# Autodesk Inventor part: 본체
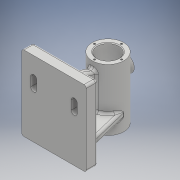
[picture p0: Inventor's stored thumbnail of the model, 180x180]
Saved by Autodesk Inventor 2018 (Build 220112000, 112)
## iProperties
Created: 2022-06
Part Number: 본체
Material: 일반
Document SubType Name: Modeling
Designer: home
Density: 1 g/cm^3
Appearance: 기본값
Author: home
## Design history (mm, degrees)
sketch "스케치1"
  geometry: L1 (-43, 50)-(43, 50); L2 (43, 50)-(43, -50); L3 (43, -50)-(-43, -50); L4 (-43, -50)-(-43, 50); L5 (-43, 50)-(43, -50); L6 (43, 50)-(-43, -50); 1 further point
  constraints: 12 end point, 2 midpoint, 2 parallel, 1 horizontal, 1 perpendicular
  dimensions: "d0" = 86 distance of L2.end L3.end; "d1" = 100 distance of L1.end L2.end
extrude "돌출1" new body sketch "스케치1" distance "d2" = 15; taper "d3" = 0 deg
sketch "스케치2"
  geometry: L1 (72, 71.237)-(72, -101.318); L2 (83.5, -50)-(93, -50); L3 (0, -50)-(15, -50) reference; L4 (83.5, -50)-(83.5, -30); L5 (93, -50)-(93, -20.658); L6 (93, -20.658)-(93, 32); L7 (93, 32)-(86.5, 32); L8 (86.5, 32)-(86.5, -30); L9 (86.5, -30)-(83.5, -30); 1 further point
  constraints: 16 end point, 3 perpendicular, 3 vertical, 2 horizontal
  dimensions: "d4" = 144 diameter of point (0, 0) L1; "d5" = 0 distance between parallel lines of L2 L3; "d6" = 23 diameter of L4 L1; "d7" = 42 diameter of L5 L1; "d8" = 82 distance of L2.end L6.end; "d9" = 29 diameter of L8 L1; "d10" = 62 vertical distance of L7.end L4.end
revolve "회전1" sketch "스케치2" stored, may be unused: angle "d11" = 90 deg
node "작업 평면1"
sketch "스케치5"
  geometry: L1 (0, 0)-(0, 15) reference; L2 (86, 15)-(0, 15) reference; L3 (8, 15)-(22, 72); L4 (43, 72)-(0, 72); L5 (43, 0)-(43, 72); L6 (0, 0)-(86, 0) reference; L7 (78, 15)-(64, 72); L8 (8, 15)-(78, 15); L9 (8, 15)-(78, 15); A1 r 21 centre (43, 72) between (22, 72) and (64, 72); A2 r 21 centre (43, 72) between (22, 72) and (64, 72)
  constraints: 12 end point, 4 point on circle, 2 centre point, 2 horizontal, 2 symmetric about line, 1 collinear, 1 concentric, 1 horizontal alignment, 1 perpendicular, 1 other
  dimensions: "d13" = 8 distance from line of L1 L3.start; "d14" = 0 distance from line of L2 L3.start; "d15" = 103.799 deg angle of L2 L3
extrude "돌출2" join sketch "스케치5" distance "d16" = 10; taper "d17" = 0 deg
node "작업 평면2"
sketch "스케치6"
  geometry: L1 (0, 0)-(0, 15) reference; L2 (100, 15)-(0, 15) reference; L3 (15, 15)-(28.823, 52.978); L4 (75, 72)-(75, 15) reference; L5 (15, 15)-(75, 15); L6 (75, 52.978)-(28.823, 52.978); L7 (18, 51)-(100, 51) reference; L8 (75, 52.978)-(75, 15); 2 further points
  constraints: 8 end point, 1 collinear, 1 parallel, 1 point on line
  dimensions: "d18" = 15 distance from line of L1 L3.start; "d19" = 0 distance from line of L2 L3.start; "d20" = 70 deg angle of L2 L3; "d21" = 0 distance from line of L4 point (75, 15); "d22" = 0 distance of L4.end point (75, 15); "d23" = 46.17723 distance of L6.start L3.end
extrude "돌출3" join sketch "스케치6" stored distance "d24" = 10; taper "d25" = 0 deg
node "작업 평면3"
sketch "스케치7"
  geometry: L1 (-21, 32)-(21, 32) reference; C1 r 11 at (0, 7); 2 further points
  constraints: 1 centre point, 1 coincident
  dimensions: "d27" = 25 distance from line of L1 point (0, 7); "d28" = 0 horizontal distance of point (0, 0) point (0, 7); "d29" = 22 diameter of C1
extrude "돌출4" join sketch "스케치7" stored distance "d30" = 10; taper "d31" = 0 deg; dims "d11" = 90 deg
sketch "스케치8"
  geometry: C1 r 11 at (0, 0) reference; C2 r 7 at (0, 0); 1 further point
  constraints: 1 centre point, 1 coincident
  dimensions: "d32" = 14 diameter of C2
extrude "돌출5" cut sketch "스케치8" distance "d33" = 4; taper "d34" = 0 deg
sketch "스케치9"
  geometry: C1 r 7 at (0, 0) reference; 1 further point
hole "구멍1" sketch "스케치9" at (0, 0) diameter "d35" = 4.917; stored, may be unused: countersink angle "d39" = 90 deg, drill point angle "d41" = 0 deg; dims "d36" = 15, "d37" = 4, "d38" = 2, "d40" = 15
fillet "모깎기1" dims "d42" = 1
sketch "스케치10"
  geometry: C1 r 14.5 at (0, 0) reference; C2 r 21 at (0, 0) reference; 2 further points
  dimensions: "d43" = 0 horizontal distance of C1.centre point (0, 18); "d44" = 18 distance of C1.centre point (0, 18)
hole "구멍2" sketch "스케치10" at (0, 18) diameter "d45" = 2.459; stored, may be unused: countersink angle "d49" = 90 deg, drill point angle "d51" = 118 deg; dims "d46" = 8, "d47" = 4, "d48" = 2, "d50" = 10
sketch "스케치11"
  geometry: C1 r 21 at (0, 0) reference; C2 r 11.5 at (0, 0) reference; 2 further points
  dimensions: "d55" = 0 horizontal distance of C1.centre point (0, 18); "d56" = 18 distance of C1.centre point (0, 18)
hole "구멍3" sketch "스케치11" at (0, 18) diameter "d57" = 2.459; stored, may be unused: countersink angle "d61" = 90 deg, drill point angle "d63" = 118 deg; dims "d58" = 8, "d59" = 4, "d60" = 2, "d62" = 10
node "작업 평면4"
sketch "스케치12"
  geometry: L1 (-43, -50)-(43, -50) reference; L2 (27, -24)-(27, -12); L3 (34, -24)-(34, -12); L4 (20, -12)-(20, -24); L5 (27, -24)-(27, -12); L6 (31, -24)-(31, -12); L7 (23, -12)-(23, -24); L8 (0, -57.693)-(0, 78.656); L9 (-20, -12)-(-20, -24); L10 (-23, -12)-(-23, -24); L11 (-31, -24)-(-31, -12); L12 (-34, -24)-(-34, -12); A1 r 7 centre (27, -24) between (20, -24) and (34, -24); A2 r 7 centre (27, -12) between (34, -12) and (20, -12); A3 r 4 centre (27, -24) between (23, -24) and (31, -24); A4 r 4 centre (27, -12) between (31, -12) and (23, -12); A5 r 7 centre (-27, -24) between (-34, -24) and (-20, -24); A6 r 7 centre (-27, -12) between (-20, -12) and (-34, -12); A7 r 4 centre (-27, -24) between (-31, -24) and (-23, -24); A8 r 4 centre (-27, -12) between (-23, -12) and (-31, -12); 3 further points
  constraints: 26 end point, 16 point on circle, 10 symmetric about line, 8 centre point, 8 tangent, 3 equal length, 2 midpoint, 2 vertical, 4 other
  dimensions: "d68" = 27 horizontal distance of L2.start point (0, 0); "d69" = 26 distance from line of L1 L2.start; "d70" = 12 distance of L2.start L2.end; "d71" = 14 diameter of A2; "d72" = 8 diameter of A4; "d73" = 0 distance from line of L8 point (0, 0)
extrude "돌출6" join sketch "스케치12" stored distance "d74" = 4; taper "d75" = 0 deg
sketch "스케치13"
  geometry: L1 (23, -12)-(23, -24) reference; L2 (31, -24)-(31, -12) reference; L3 (-23, -24)-(-23, -12) reference; L4 (-31, -12)-(-31, -24) reference; A1 r 4 centre (27, -24) between (23, -24) and (31, -24) reference; A2 r 4 centre (27, -12) between (31, -12) and (23, -12) reference; A3 r 4 centre (-27, -12) between (-23, -12) and (-31, -12) reference; A4 r 4 centre (-27, -24) between (-31, -24) and (-23, -24) reference; 1 further point
extrude "돌출7" cut sketch "스케치13" distance "d76" = 18; taper "d77" = 0 deg
fillet "모깎기2" dims "d78" = 3
fillet "모깎기3" dims "d79" = 3
fillet "모깎기4" dims "d80" = 3
fillet "모깎기5" dims "d81" = 3
fillet "모깎기6" dims "d82" = 3
chamfer "모따기1" distance "d83" = 1; stored, may be unused: second distance "d84" = 2, angle "d85" = 45 deg
node "작업 평면5"
sketch "스케치14"
  geometry: L1 (80, 0)-(0, 0) reference; 2 further points
  constraints: 1 other
  dimensions: "d87" = 6 distance from line of L1 point (40, 6); "d88" = 0 horizontal distance of point (40, 6) point (40, 0)
feature "엠보싱1" sketch "스케치14" dims "d0" = 86, "d1" = 100, "d89" = 0.5, "d90" = 0
node "솔리드1"
pattern_circular "원형 패턴1" dims angle "d53" = 360 deg
pattern_circular "원형 패턴2" dims angle "d65" = 360 deg
node "투영된 루프1"
node "투영된 루프2"
node "투영된 루프3"
node "투영된 루프4"
node "투영된 루프5"
node "투영된 루프6"
other parameters: "d12" = -15, "d26" = -96, "d67" = 3, "d86" = 1
